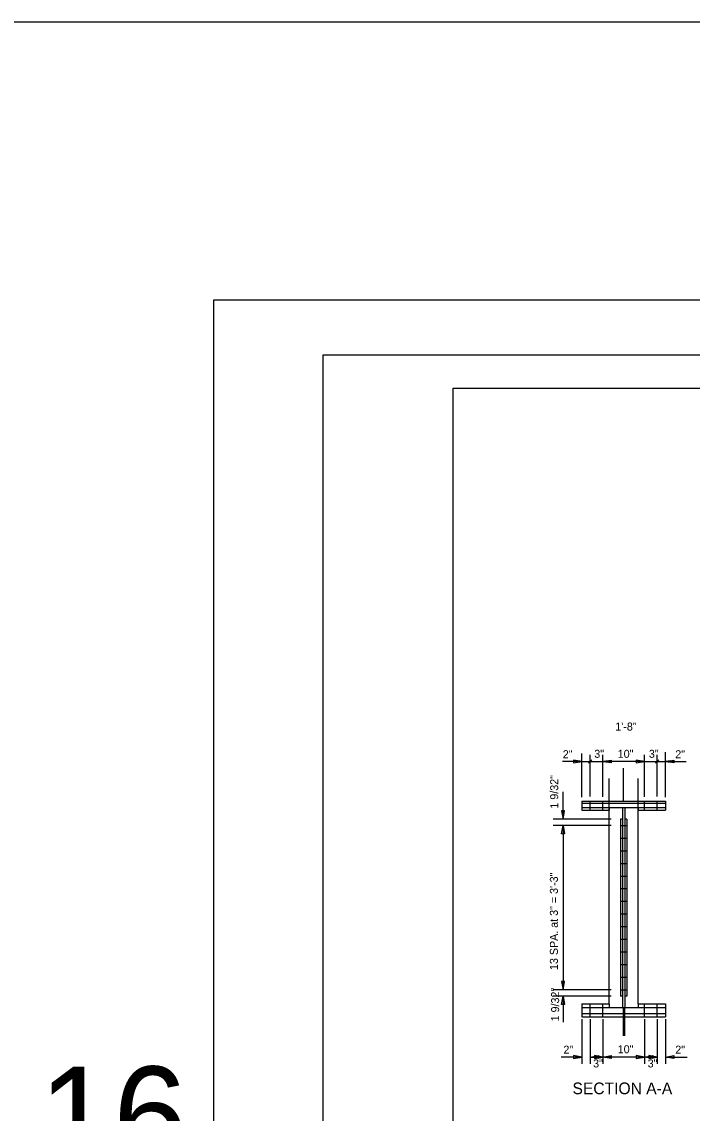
# Model space of a CAD drawing. Extents: x 4944 to 17449, y 3824 to 49087.
# Drawn here: x 6803 to 7767, y 40051 to 41622 of the extents above; entities that cross this region are included whole.
import ezdxf

# ---------------------------------------------------------------- set-up
doc = ezdxf.new("R2010")
doc.units = 0
for name, color, linetype in [('1', 7, 'Continuous'), ('36_S_LINES', 7, 'Continuous'), ('37_S_TXT', 7, 'Continuous'), ('3A', 7, 'Continuous'), ('BEAM', 7, 'Continuous'), ('DIM', 7, 'Continuous'), ('HATCH', 7, 'Continuous'), ('Level 14', 7, 'Continuous'), ('Level 25', 7, 'Continuous')]:
    doc.layers.add(name, color=color, linetype=linetype)

msp = doc.modelspace()

# ---------------------------------------------------------------- linework, layer by layer
at = {"layer": '1'}
for points in [[(7620.5, 40487.4), (7620.5, 40500.5)], [(7638.7, 40487.4), (7638.7, 40500.5)], [(7698.7, 40487.4), (7698.7, 40500.5)], [(7716.9, 40487.4), (7716.9, 40500.5)], [(7664.2, 40465.4), (7673.3, 40465.4)], [(7664.2, 40447.2), (7673.3, 40447.2)], [(7664.2, 40429), (7673.3, 40429)], [(7664.2, 40410.8), (7673.3, 40410.8)], [(7664.2, 40392.6), (7673.3, 40392.6)], [(7664.2, 40374.4), (7673.3, 40374.4)], [(7664.2, 40356.3), (7673.3, 40356.3)], [(7664.2, 40338.1), (7673.3, 40338.1)], [(7664.2, 40319.9), (7673.3, 40319.9)], [(7664.2, 40301.7), (7673.3, 40301.7)], [(7664.2, 40283.5), (7673.3, 40283.5)], [(7664.2, 40265.3), (7673.3, 40265.3)], [(7664.2, 40247.1), (7673.3, 40247.1)], [(7664.2, 40228.9), (7673.3, 40228.9)], [(7620.5, 40189.7), (7620.5, 40208.8)], [(7638.7, 40189.7), (7638.7, 40208.8)], [(7698.7, 40189.7), (7698.7, 40208.8)], [(7716.9, 40189.7), (7716.9, 40208.8)]]:
    msp.add_lwpolyline(points, dxfattribs=at)
at = {"layer": '36_S_LINES'}
for p, q in [((7608.7, 40506.1), (7608.7, 40569.1)), ((7728.7, 40506.1), (7728.7, 40570.8)), ((7608.7, 40557.3), (7580.6, 40557.3)), ((7608.7, 40557.3), (7638.7, 40557.3)), ((7623, 40559.8), (7618.1, 40554.9)), ((7698.7, 40557.3), (7638.7, 40557.3)), ((7698.7, 40557.3), (7728.7, 40557.3)), ((7719.4, 40559.8), (7714.5, 40554.9)), ((7728.7, 40557.3), (7758.6, 40557.3)), ((7581.5, 40474.5), (7581.5, 40513.8)), ((7650.7, 40474.5), (7567.5, 40474.5)), ((7581.5, 40465.4), (7581.5, 40228.9)), ((7650.7, 40219.8), (7567.5, 40219.8)), ((7581.5, 40219.8), (7581.5, 40182.3)), ((7608.7, 40186.6), (7608.7, 40122.5)), ((7728.7, 40186.6), (7728.7, 40122.5)), ((7608.7, 40132.1), (7578.9, 40132.1)), ((7620.5, 40132.1), (7638.7, 40132.1)), ((7698.7, 40132.1), (7638.7, 40132.1)), ((7716.9, 40132.1), (7698.7, 40132.1)), ((7728.7, 40132.1), (7760.3, 40132.1))]:
    msp.add_line(p, q, dxfattribs=at)
for points in [[(7596.6, 40559.4), (7596.6, 40555.3), (7608.7, 40557.3)], [(7600.7, 40556.3), (7600.7, 40558.4), (7608.7, 40557.3)], [(7600.7, 40558.4), (7600.7, 40556.3), (7608.7, 40557.3)], [(7650.9, 40559.4), (7650.9, 40555.3), (7638.7, 40557.3)], [(7646.7, 40556.3), (7646.7, 40558.4), (7638.7, 40557.3)], [(7646.7, 40558.4), (7646.7, 40556.3), (7638.7, 40557.3)], [(7686.6, 40559.4), (7686.6, 40555.3), (7698.7, 40557.3)], [(7690.7, 40556.3), (7690.7, 40558.4), (7698.7, 40557.3)], [(7690.7, 40558.4), (7690.7, 40556.3), (7698.7, 40557.3)], [(7740.9, 40559.4), (7740.9, 40555.3), (7728.7, 40557.3)], [(7736.7, 40556.3), (7736.7, 40558.4), (7728.7, 40557.3)], [(7736.7, 40558.4), (7736.7, 40556.3), (7728.7, 40557.3)], [(7583.5, 40486.6), (7579.5, 40486.6), (7581.5, 40474.5)], [(7583.5, 40453.3), (7579.5, 40453.3), (7581.5, 40465.4)], [(7583.5, 40241), (7579.5, 40241), (7581.5, 40228.9)], [(7583.5, 40207.7), (7579.5, 40207.7), (7581.5, 40219.8)], [(7596.6, 40134.1), (7596.6, 40130.1), (7608.7, 40132.1)], [(7600.7, 40133.1), (7600.7, 40131.1), (7608.7, 40132.1)], [(7632.7, 40134.1), (7632.7, 40130.1), (7620.5, 40132.1)], [(7628.5, 40133.1), (7628.5, 40131.1), (7620.5, 40132.1)], [(7626.6, 40134.1), (7626.6, 40130.1), (7638.7, 40132.1)], [(7630.7, 40133.1), (7630.7, 40131.1), (7638.7, 40132.1)], [(7650.9, 40134.1), (7650.9, 40130.1), (7638.7, 40132.1)], [(7646.7, 40133.1), (7646.7, 40131.1), (7638.7, 40132.1)], [(7686.6, 40134.1), (7686.6, 40130.1), (7698.7, 40132.1)], [(7690.7, 40133.1), (7690.7, 40131.1), (7698.7, 40132.1)], [(7710.9, 40134.1), (7710.9, 40130.1), (7698.7, 40132.1)], [(7706.7, 40133.1), (7706.7, 40131.1), (7698.7, 40132.1)], [(7704.8, 40134.1), (7704.8, 40130.1), (7716.9, 40132.1)], [(7708.9, 40133.1), (7708.9, 40131.1), (7716.9, 40132.1)], [(7740.9, 40134.1), (7740.9, 40130.1), (7728.7, 40132.1)], [(7736.7, 40133.1), (7736.7, 40131.1), (7728.7, 40132.1)]]:
    msp.add_lwpolyline(points, close=True, dxfattribs=at)
at = {"layer": '37_S_TXT'}
msp.add_lwpolyline([(7079, 41222), (10535, 41222), (10535, 38917.9), (7079, 38917.9)], close=True, dxfattribs=at)
at = {"layer": '3A'}
for p, q in [((7620.5, 40507.2), (7620.5, 40567)), ((7638.7, 40506.4), (7638.7, 40567)), ((7698.7, 40506.4), (7698.7, 40567)), ((7716.9, 40507.2), (7716.9, 40567)), ((7650.7, 40465.4), (7567.5, 40465.4)), ((7650.7, 40228.9), (7567.5, 40228.9)), ((7620.5, 40186.6), (7620.5, 40122.5)), ((7638.7, 40186.6), (7638.7, 40122.5)), ((7698.7, 40186.6), (7698.7, 40122.5)), ((7716.9, 40186.6), (7716.9, 40122.5))]:
    msp.add_line(p, q, dxfattribs=at)
at = {"layer": 'DEFPOINTS'}
for p, q in [((7668.7, 40500.5), (7668.7, 40547.9)), ((7647.8, 40208.8), (7647.8, 40532.9)), ((7689.6, 40208.8), (7689.6, 40532.9)), ((7667.8, 40203.2), (7667.8, 40162.7)), ((7669.7, 40203.2), (7669.7, 40162.7)), ((7668.7, 40189.7), (7668.7, 40162.7))]:
    msp.add_line(p, q, dxfattribs=at)
at = {"layer": 'DIM'}
msp.add_lwpolyline([(7236.2, 41142.8), (10500.2, 41142.8), (10500.2, 39030.7), (7236.2, 39030.7)], close=True, dxfattribs=at)
at = {"layer": 'HATCH'}
msp.add_line((5851.1, 41621.9), (16384.1, 41621.9), dxfattribs=at)
at = {"layer": 'Level 14'}
msp.add_lwpolyline([(10447.4, 39078.7), (7423.4, 39078.7), (7423.4, 41094.8), (10447.4, 41094.8)], close=True, dxfattribs=at)
at = {"layer": 'Level 25'}
for p, q in [((7608.7, 40500.5), (7728.7, 40500.5)), ((7608.7, 40500.5), (7608.7, 40487.4)), ((7608.7, 40497.2), (7728.7, 40497.2)), ((7608.7, 40491.2), (7728.7, 40491.2)), ((7647.8, 40491.2), (7647.8, 40487.4)), ((7667.2, 40491.2), (7667.2, 40203.2)), ((7670.3, 40491.2), (7670.3, 40203.2)), ((7689.6, 40491.2), (7689.6, 40487.4)), ((7728.7, 40500.5), (7728.7, 40487.4)), ((7608.7, 40487.4), (7647.8, 40487.4)), ((7689.6, 40487.4), (7728.7, 40487.4)), ((7664.2, 40474.5), (7664.2, 40219.8)), ((7667.2, 40474.5), (7664.2, 40474.5)), ((7673.3, 40474.5), (7670.3, 40474.5)), ((7673.3, 40474.5), (7673.3, 40219.8)), ((7608.7, 40208.8), (7647.8, 40208.8)), ((7608.7, 40208.8), (7608.7, 40189.7)), ((7647.8, 40208.8), (7647.8, 40203.2)), ((7667.2, 40219.8), (7664.2, 40219.8)), ((7673.3, 40219.8), (7670.3, 40219.8)), ((7689.6, 40208.8), (7728.7, 40208.8)), ((7689.6, 40208.8), (7689.6, 40203.2)), ((7728.7, 40208.8), (7728.7, 40189.7)), ((7608.7, 40203.2), (7728.7, 40203.2)), ((7608.7, 40194.9), (7728.7, 40194.9)), ((7608.7, 40189.7), (7728.7, 40189.7))]:
    msp.add_line(p, q, dxfattribs=at)

# ---------------------------------------------------------------- texts
at = {"layer": '3A'}
for s, p in [('2"', (7581.1, 40562.1)), ('3"', (7626.5, 40562.7)), ('10"', (7660.2, 40562.7)), ('3"', (7705, 40562.7)), ('2"', (7743, 40562.1)), ('2"', (7582.1, 40136.9)), ('10"', (7660.2, 40137.5)), ('2"', (7743, 40136.9)), ('3"', (7624.8, 40117.1)), ('3"', (7703.3, 40117.1))]:
    msp.add_text(s, height=11.52, dxfattribs=at).set_placement(p)
for s, p in [('1 9/32"', (7574.6, 40489.6)), ('13 SPA. at 3" = 3\'-3"', (7574.1, 40257.3)), ('1 9/32"', (7575.9, 40183.4))]:
    msp.add_text(s, height=11.52, rotation=90, dxfattribs=at).set_placement(p)
at = {"layer": 'BEAM'}
msp.add_text('SECTION A-A', height=16.8, dxfattribs=at).set_placement((7595.1, 40078.6))
at = {"layer": 'DEFPOINTS'}
msp.add_text('1\'-8"', height=11.52, dxfattribs=at).set_placement((7656.7, 40601.9))
at = {"layer": 'HATCH'}
msp.add_text('16', height=144, dxfattribs=at).set_placement((6827.3, 39974.4))

doc.saveas('drawing.dxf')
